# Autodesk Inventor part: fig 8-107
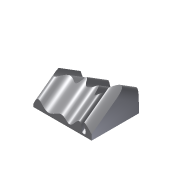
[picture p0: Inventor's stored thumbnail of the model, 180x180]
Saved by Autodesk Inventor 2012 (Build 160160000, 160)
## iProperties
Shininess: 64.0
Length Units: 11269
Angle Units: 11279
Time Units: 11290
Mass Units: 11283
Length Display Precision: 3
Angle Display Precision: 2
Compacted: True
Part Number: fig 8-107
Document SubType Name: Modeling
Created: 2002-12
Designer: deepak
Density: 1 g/cm^3
Material: Default
Density: 0.0
Volumn: 0.0
Area: 0.0
PropertySet Name: Model Information
Control State: 0
Master: False
Checked Out: False
Author: deepak
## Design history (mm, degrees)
sketch "Sketch1"
  geometry: L1 (-33.715, 26.527)-(30.916, 26.527); L2 (30.916, 26.527)-(30.916, -25.891); L3 (30.916, -25.891)-(-33.715, -25.891); L4 (-33.715, -25.891)-(-33.715, 26.527)
  constraints: 8 end point, 2 parallel, 1 horizontal, 1 perpendicular
extrude "Extrusion1" new body sketch "Sketch1" distance "d0" = 20; taper "d1" = 0 deg
sketch "Sketch2"
  geometry: L1 (-44.187, -5.757)-(15.849, 38.63)
  constraints: 2 end point
workplane "Work Plane1"
sketch "Sketch3"
  geometry: L1 (33.715, -6.248)-(33.715, 9.834) reference; L2 (-30.916, -6.248)-(-30.916, 9.834) reference; 10 further points
  constraints: 2 point on line, 11 other
feature "SweepSrf1" sketch "Sketch3" dims "d2" = 0
sketch "Sketch4"
  geometry: L1 (-26.819, 39.395)-(38.245, -1.181)
  constraints: 2 end point
workplane "Work Plane2"
sketch "Sketch5"
  geometry: L1 (-30.916, -5.198)-(-30.916, 11.772) reference; L2 (33.715, -5.198)-(33.715, 11.772) reference; 10 further points
  constraints: 2 point on line, 10 other
feature "SweepSrf2" sketch "Sketch5" dims "d3" = 0
feature "Replace Face4"
body "Solid1"
body "Srf1"
body "Srf2"
